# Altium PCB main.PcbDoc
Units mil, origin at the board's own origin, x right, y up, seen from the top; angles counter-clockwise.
Board outline 6000 x 4000 mil, 2 copper layers (Top Layer, Bottom Layer); 22 components, 11 nets, 84 pads, 0 vias.
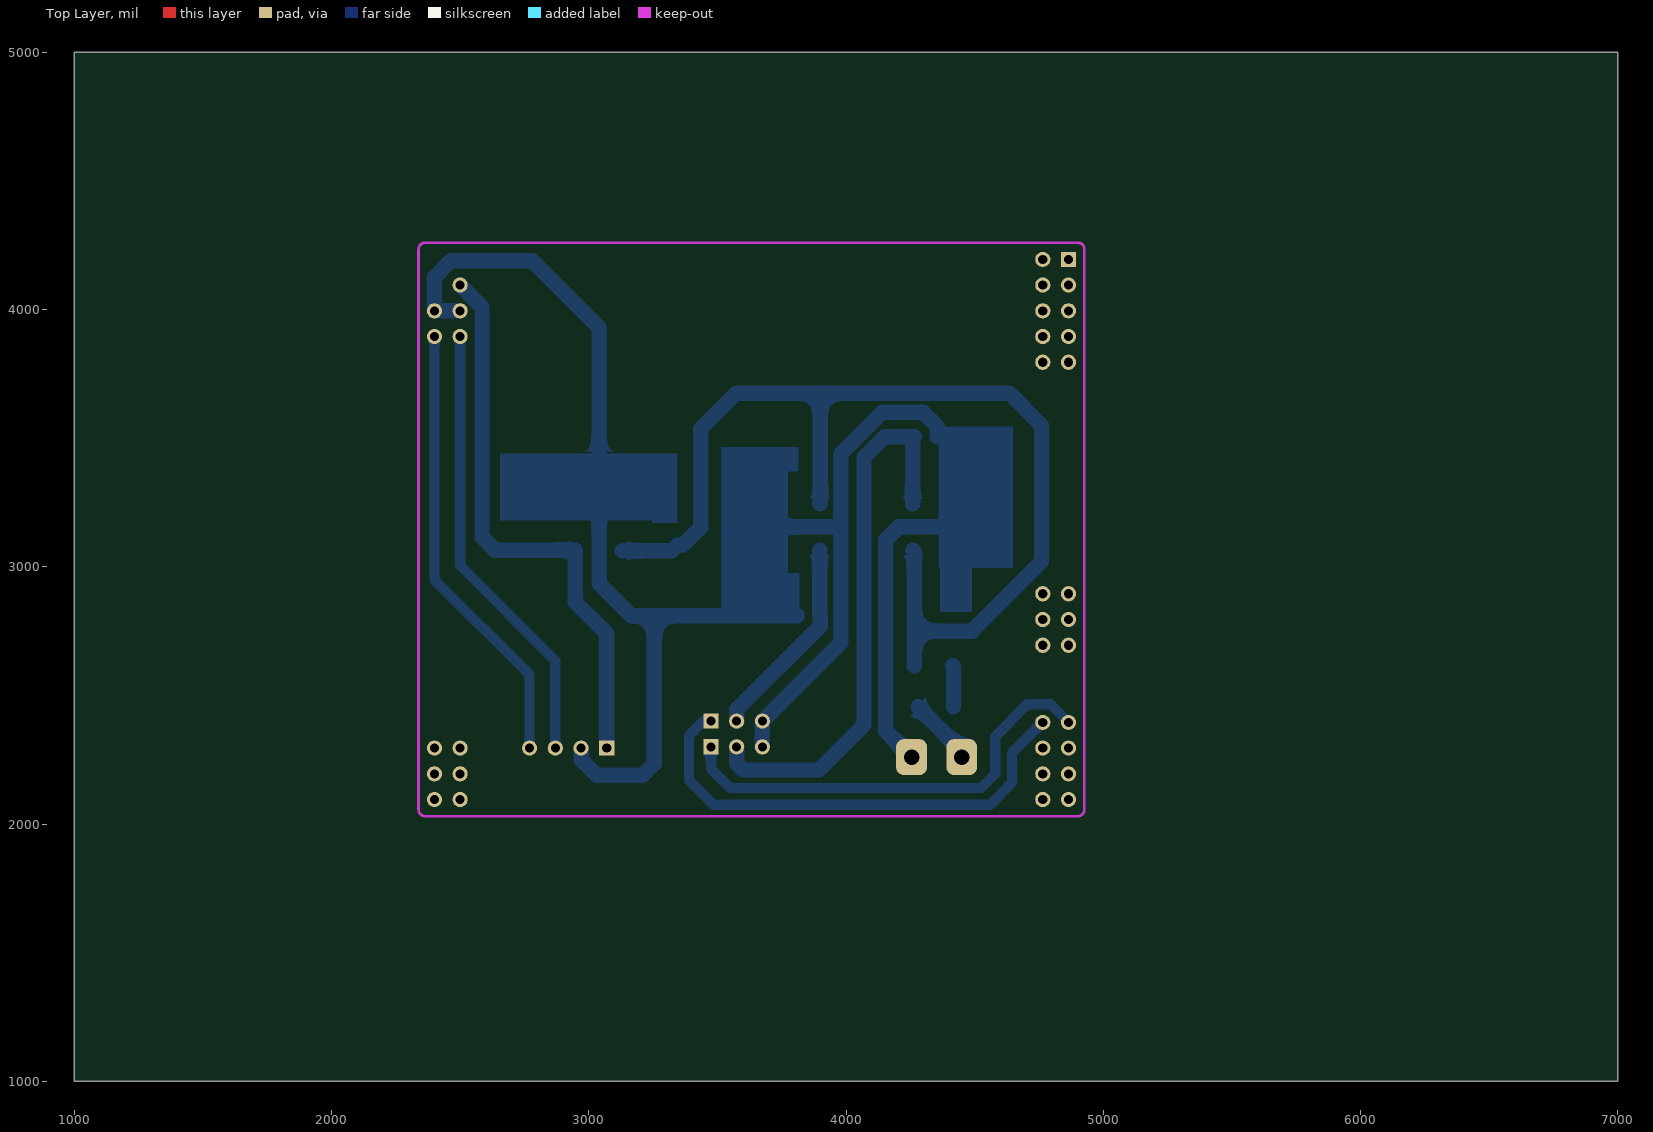
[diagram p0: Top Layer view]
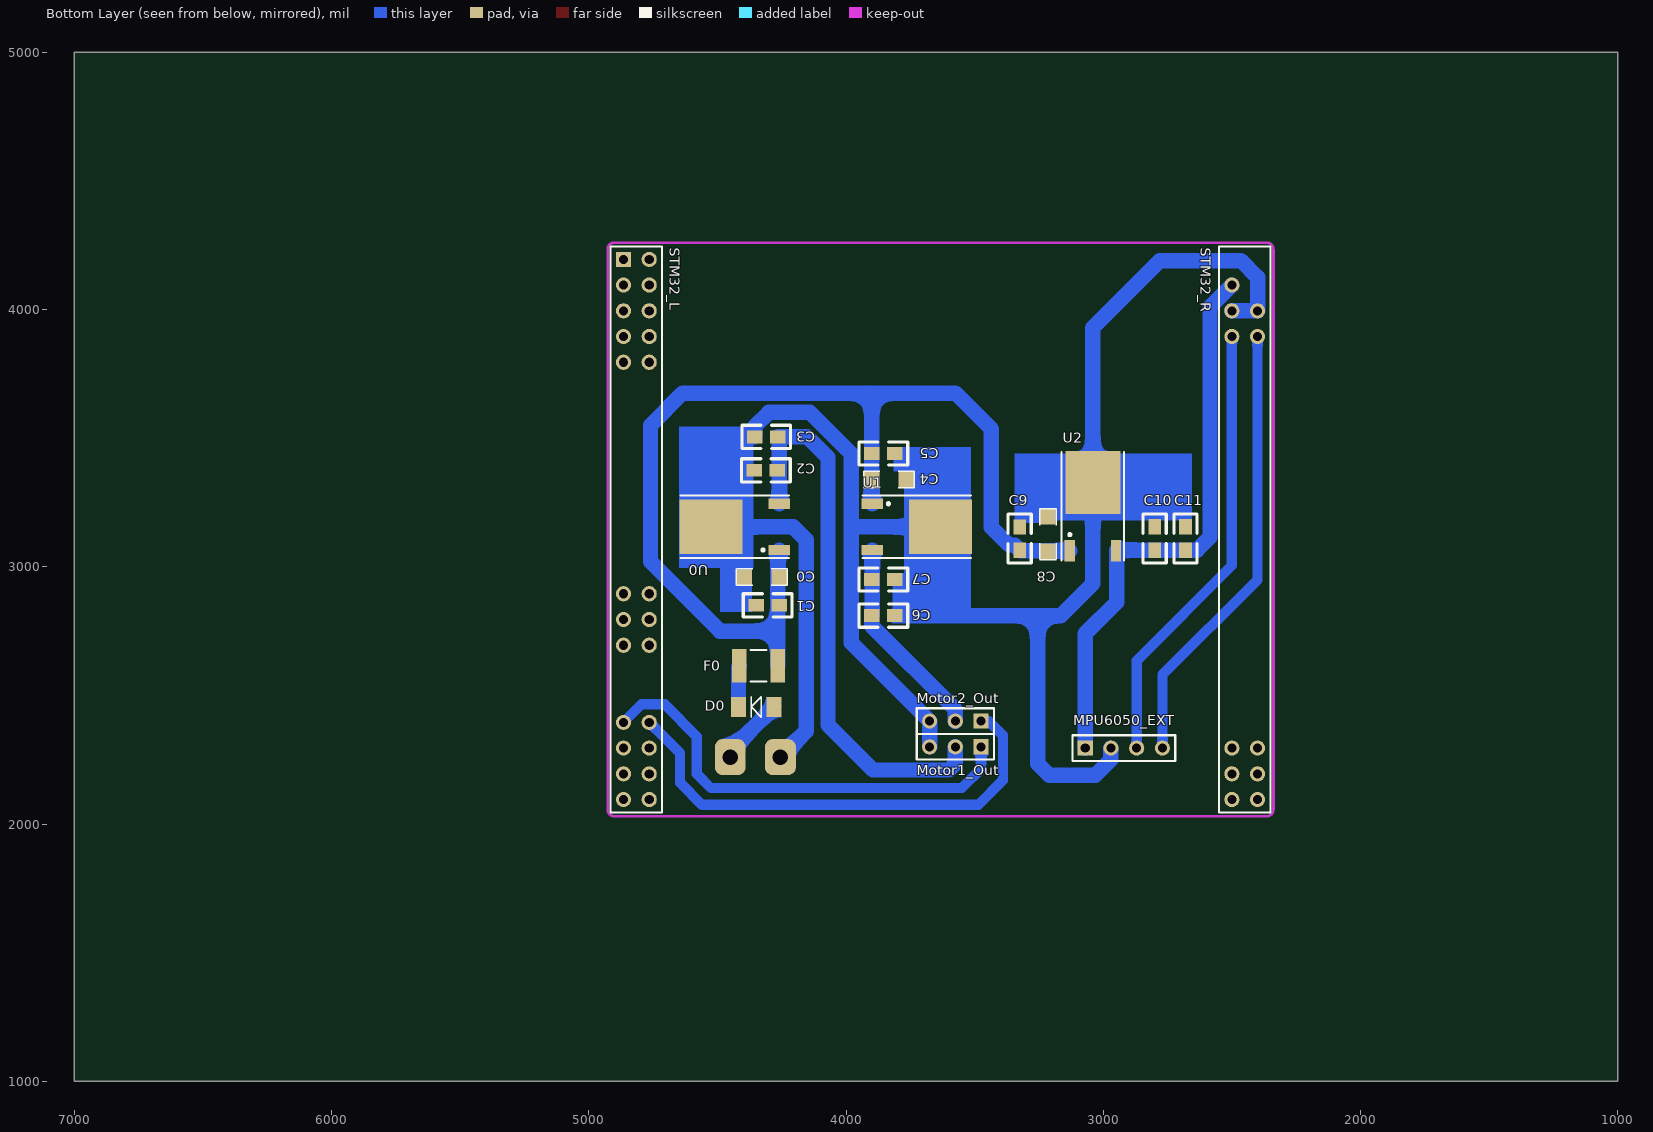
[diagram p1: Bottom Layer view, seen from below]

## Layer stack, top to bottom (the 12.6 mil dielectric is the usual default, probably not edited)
Top Solder: solder mask 0.4, Solder Resist, Dk 3.5
Top Layer: signal copper 1.4
Dielectric 1: dielectric 12.6, FR-4, Dk 4.8
Bottom Layer: signal copper 1.4
Bottom Solder: solder mask 0.4, Solder Resist, Dk 3.5

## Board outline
1000,1000 7000,1000 7000,5000 1000,5000

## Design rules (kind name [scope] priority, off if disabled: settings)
Clearance [All] p1: gap=10
PolygonConnect [All] p1: connectstyle=Relief reliefconductorwidth=10 reliefentries=4 polygonreliefangle="90 Angle" airgapwidth=10
RoutingVias [All] p1: holewidth=28 width=50 viastyle="Through Hole" minholewidth=28 minwidth=50 maxholewidth=28 maxwidth=50
SolderMaskExpansion [All] p1: expansion=4
Width [All] p1: maxlimit=80 minlimit=40 preferedwidth=40
30 further rules are at their usual default settings.

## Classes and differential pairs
component class main: C8 C9 C10 C11 D0 F0 Motor1_Out Motor2_Out MPU6050_EXT STM32_L U2

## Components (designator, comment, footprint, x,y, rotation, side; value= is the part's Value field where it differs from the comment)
C0 "Cap Pol1" 1206A 4259.96,2958.82 r0 bottom
C1 "Cap Semi" 0805 4350,2850 r180 bottom
C2 "Cap Semi" 0805 4356.98,3374.76 r180 bottom
C3 "Cap Semi" 0805 4355.41,3504.76 r180 bottom
C4 "Cap Pol1" 1206A 3900,3340 r180 bottom
C5 "Cap Semi" 0805 3809.59,3440.24 r0 bottom
C6 "Cap Semi" 0805 3809.59,2810.24 r0 bottom
C7 "Cap Semi" 0805 3809.59,2950.24 r0 bottom
C8 "Cap Pol1" 1206A 3216.18,3059.96 r90 bottom
C9 "Cap Semi" 0805 3325,3155 r270 bottom
C10 "Cap Semi" 0805 2800.24,3155.41 r270 bottom
C11 "Cap Semi" 0805 2680.24,3155.41 r270 bottom
D0 "Diode" DIODE-1206 4280,2455 r0 bottom
F0 "Fuse 2" 1812 4340,2615 r180 bottom
Motor1_Out "Header 3" HDR1X3 3475,2300 r0 bottom
Motor2_Out "Header 3" HDR1X3 3475,2400 r0 bottom
MPU6050_EXT "Header 4" HDR1X4 3070,2295 r180 bottom
STM32_L "Header 22X2" HDR2X22#1 4865,4195 r270 bottom
STM32_R "Header 22X2" HDR2X22#2 2500,4195 r270 bottom
U0 "L78M05ABDT" TO-252 4392.13,3155 r90 bottom
U1 "L78M05ABDT" TO-252 3765,3155 r270 bottom
U2 "L78M05ABDT" TO-252 3040,3195 r180 bottom

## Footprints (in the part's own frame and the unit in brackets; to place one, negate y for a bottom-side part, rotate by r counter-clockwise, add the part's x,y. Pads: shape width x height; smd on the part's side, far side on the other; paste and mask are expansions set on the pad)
0805 [mil]
  rect 60x50 smd: 1(0.41,0.24) 2(90.41,0.24)
  silkscreen extent -50,-45 140,45
1206A [mil]
  rect 60x60 smd: 1(0.04,-1.18) 2(135.04,-1.18)
  silkscreen extent -32,-33 166,31
1812 [mm] "Chip Capacitor, Body 4.5x3.2mm, IPC High Density"
  rect 1.4x3.3 smd: 1(-1.9,0) 2(1.9,0)
  silkscreen extent -0.8,-1.55 0.8,1.55, body extent -2.4,-1.7 2.4,1.7, height 1.4
DIODE-1206 [mm] "玻璃封装二极管"
  rect 1.5x2 smd: 1(0,0) 2(3.5,0)
  silkscreen extent 1.25,-1 2.25,1
HDR1X3 [mm] "Connector; Header; 3 Position"
  rect 1.5x1.5 hole 0.9: 1(0,0)
  round 1.5 hole 0.9: 2(2.54,0) 3(5.08,0)
  silkscreen extent -1.27,-1.27 6.35,1.27
HDR1X4 [mm] "Connector; Header; 4 Position"
  rect 1.5x1.5 hole 0.9: 1(0,0)
  round 1.5 hole 0.9: 2(2.54,0) 3(5.08,0) 4(7.62,0)
  silkscreen extent -1.27,-1.27 8.89,1.27
HDR2X22#1 [mm] "Connector; Header; 22x2 Position"
  rect 1.5x1.5 hole 0.9: 1(0,0)
  round 1.5 hole 0.9: 2(0,2.54) 3(2.54,0) 4(2.54,2.54) 5(5.08,0) 6(5.08,2.54) 7(7.62,0) 8(7.62,2.54) 9(10.16,0) 10(10.16,2.54) 27(33.02,0) 28(33.02,2.54) 29(35.56,0) 30(35.56,2.54) 31(38.1,0) 32(38.1,2.54) 37(45.72,0) 38(45.72,2.54) 39(48.26,0) 40(48.26,2.54) 41(50.8,0) 42(50.8,2.54) 43(53.34,0) 44(53.34,2.54)
  silkscreen extent -1.27,-1.27 54.61,3.81
HDR2X22#2 [mm] "Connector; Header; 22x2 Position"
  round 1.5 hole 0.9: 3(2.54,0) 5(5.08,0) 6(5.08,2.54) 7(7.62,0) 8(7.62,2.54) 39(48.26,0) 40(48.26,2.54) 41(50.8,0) 42(50.8,2.54) 43(53.34,0) 44(53.34,2.54)
  silkscreen extent -1.27,-1.27 54.61,3.81
TO-252 [mm] "D-PAK/TO-252-AA; 3 Leads (1 Cropped); Body 10.1 (inc. leads) x 6.6 mm (LxW max)"
  rect 1x2.1 smd: 1(-2.285,-3.375) 3(2.285,-3.375)
  rect 5.4x6.2 smd: 4(0,3.375)
  silkscreen extent -3.09,-4.32 3.09,6.38

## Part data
C0 C4 C8: "Polarized Capacitor (Radial)"
C1 C2 C3 C5 C6 C7 C9 C10 C11: "Capacitor (Semiconductor SIM Model)"
D0: "Default Diode"
F0: "Fuse"
Motor1_Out Motor2_Out: "Header, 3-Pin"
MPU6050_EXT: "Header, 4-Pin"
STM32_L STM32_R: "Header, 22-Pin, Dual row"
U0 U1 U2: "Precision 500mA Regulator"

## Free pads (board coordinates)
  rrect50% 120x140 hole 60: 0(4255,2260) 0(4450,2260)

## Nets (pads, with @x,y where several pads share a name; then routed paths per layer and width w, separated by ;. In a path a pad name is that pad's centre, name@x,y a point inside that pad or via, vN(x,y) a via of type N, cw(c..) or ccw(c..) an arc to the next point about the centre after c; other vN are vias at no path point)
5V_1: C2.2 C3.2 Motor1_Out.2 U0.3 | length 2173.4
  Bottom Layer w60: Motor1_Out.2 3575,2235 3600,2210 3895,2210 4070,2385 4070,3425 4150,3505 C3.2 4259.25,3499.25 U0.3
5V_2: C6.2 C7.2 Motor2_Out.2 U1.3 | length 800.5
  Bottom Layer w40: C6.2@3897.87,2812.13 C6.2
  Bottom Layer w60: Motor2_Out.2 3575,2445 3900,2770 C6.2 ; C6.2@3897.87,2812.13 U1.3
5V_3: C10.2 C11.2 MPU6050_EXT.1 STM32_R.3 U2.3 | length 2219
  Bottom Layer w60: STM32_R.3 2585,4010 2585,3115 2635,3065 C11.2 C10.2 2947.17,3065 2947.17,2862.83 3070,2740 MPU6050_EXT.1
B4_ROLL: Motor1_Out.1 STM32_L.37 | length 1754.6
  Bottom Layer w40: Motor1_Out.1 3475,2215 3550,2140 4525,2140 4580,2195 4580,2340 4705,2465 4795,2465 STM32_L.37
B5_PITCH: Motor2_Out.1 STM32_L.38 | length 1897
  Bottom Layer w40: Motor2_Out.1 3445,2400 3390,2345 3390,2170 3485,2075 4560,2075 4645,2160 4645,2275 STM32_L.38
B10_SCL: MPU6050_EXT.3 STM32_R.7 | length 1753.3
  Bottom Layer w40: STM32_R.7 2500,3005 2870,2635 MPU6050_EXT.3
B11_SDA: MPU6050_EXT.4 STM32_R.8 | length 1753.3
  Bottom Layer w40: STM32_R.8 2400,2950 2770,2580 MPU6050_EXT.4
GND: C0.2 C1.1 C2.1 C3.1 C4.2 C5.1 C6.1 C7.1 C8.2 C9.1 C10.1 C11.1 Motor1_Out.3 Motor2_Out.3 MPU6050_EXT.2 pad.0@4255,2260 STM32_R.5 STM32_R.6 U0.4 U1.4 U2.4 | length 7165.3
  Bottom Layer w60: STM32_R.5 STM32_R.6 2400,4125 2465,4190 2780,4190 3040,3930 U2.4 3040,2935 3165,2810 3255,2810 ; MPU6050_EXT.2 2970,2250 3030,2190 3210,2190 3255,2235 3255,2810 ; U1.4 3980,3155 ; Motor1_Out.3 Motor2_Out.3 3980,2705 3980,3155 ; C6.1 3255,2810 ; pad.0@4255,2260 4155,2360 4155,3105 4205,3155 U0.4 ; C3.1 4355,3545 4300,3600 4140,3600 3980,3440 3980,3155
NetD0_2: D0.2 F0.1 | length 161.2
  Bottom Layer w60: F0.1 4417.8,2612.01 D0.2
VCC: C0.1 C1.2 C4.1 C5.2 C8.1 C9.2 F0.2 U0.1 U1.1 U2.1 | length 4179.4
  Bottom Layer w60: U2.1 3322.29,3062.13 C9.2 3344.76,3084.59 3366.32,3084.59 3435,3153.27 3435,3535 3575,3675 3900,3675 ; U1.1 3900,3247.09 C5.2 3900,3675 ; U0.1 4265.2,3059.09 4265.2,2750 ; F0.2 4265.2,2750 ; 3900,3675 4635,3675 4760,3550 4760,3020 4490,2750 4265.2,2750
VIN: D0.1 pad.0@4450,2260 | length 265.4
  Bottom Layer w60: D0.1 4450,2285 pad.0@4450,2260
pads on no net: STM32_L.1 STM32_L.2 STM32_L.3 STM32_L.4 STM32_L.5 STM32_L.6 STM32_L.7 STM32_L.8 STM32_L.9 STM32_L.10 STM32_L.27 STM32_L.28 STM32_L.29 STM32_L.30 STM32_L.31 STM32_L.32 STM32_L.39 STM32_L.40 STM32_L.41 STM32_L.42 STM32_L.43 STM32_L.44 STM32_R.39 STM32_R.40 STM32_R.41 STM32_R.42 STM32_R.43 STM32_R.44

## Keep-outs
Keep-Out Layer:
  lines w10: 2338.07,2056.93 ccw(c2365,2056.93) 2365,2030 4900,2030 ccw(c4900,2056.93) 4926.93,2056.93 4926.93,2106.93 4926.93,4233.07 ccw(c4900,4233.07) 4900,4260 2365,4260 ccw(c2365,4233.07) 2338.07,4233.07 2338.07,2056.93

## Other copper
Bottom Layer:
  rectangle net GND: 3245,3170 3345,3195
  rectangle net GND: 3710,2780 3820,2975
  rectangle net GND: 3695,3370 3815,3465
  rectangle net GND: 3515,2780 3775,3465
  rectangle net GND: 2655,3180 3345,3440
  rectangle net GND: 4365,2825 4490,3010
  rectangle net GND: 4360,2995 4650,3545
